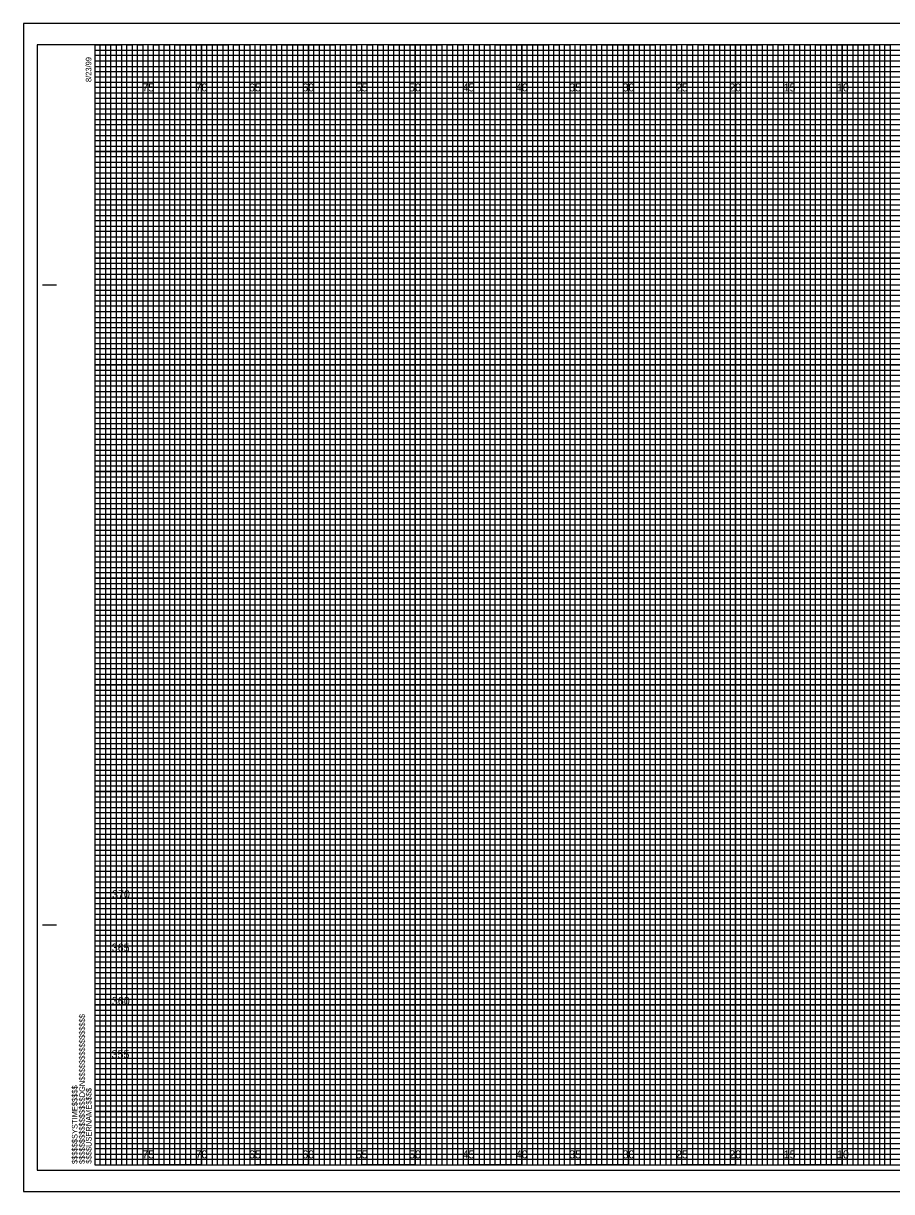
# Model space of a CAD drawing. Extents: x -7 to 266, y -5 to 437.
# Drawn here: x -6.7 to 74.6, y 327.5 to 437 of the extents above; entities that cross this region are included whole.
import ezdxf

# ---------------------------------------------------------------- set-up
doc = ezdxf.new("R2010")
doc.units = 0
for name, color, linetype in [('Exist XS Center Line Elevation Label', 7, 'Continuous'), ('Exist XS Ground Line', 7, 'Continuous'), ('Prop XS Finish Grade', 7, 'Continuous'), ('Prop XS Finish Grade Concrete', 7, 'Continuous'), ('Prop XS Finish Grade Earthwork', 7, 'Continuous'), ('Prop XS Hydro Elevations', 7, 'Continuous'), ('Prop XS Pvmt Edge Slope', 7, 'Continuous'), ('Prop XS SE Text', 7, 'Continuous'), ('Prop XS SS Elevation Text', 7, 'Continuous'), ('Prop XS Subgrade Earthwork', 7, 'Continuous'), ('Typical Guardrail CELL', 7, 'Continuous')]:
    doc.layers.add(name, color=color, linetype=linetype)

msp = doc.modelspace()

# ---------------------------------------------------------------- linework, layer by layer
at = {"layer": 'Exist XS Center Line Elevation Label'}
for points in [[(0, 435), (2.5, 435), (2.5, 330), (7.5, 330), (7.5, 435), (12.5, 435), (12.5, 330), (17.5, 330), (17.5, 435), (22.5, 435), (22.5, 330), (27.5, 330), (27.5, 435), (32.5, 435), (32.5, 330), (37.5, 330), (37.5, 435), (42.5, 435), (42.5, 330), (47.5, 330), (47.5, 435), (52.5, 435), (52.5, 330), (57.5, 330), (57.5, 435), (62.5, 435), (62.5, 330), (67.5, 330), (67.5, 435), (72.5, 435), (72.5, 330), (77.5, 330)], [(0, 432.5), (137.5, 432.5)], [(0, 422.5), (160, 422.5), (160, 427.5), (0, 427.5)], [(0, 412.5), (160, 412.5), (160, 417.5), (0, 417.5)], [(0, 402.5), (160, 402.5), (160, 407.5), (0, 407.5)], [(0, 392.5), (160, 392.5), (160, 397.5), (0, 397.5)], [(0, 382.5), (160, 382.5), (160, 387.5), (0, 387.5)], [(0, 372.5), (160, 372.5), (160, 377.5), (0, 377.5)], [(0, 362.5), (160, 362.5), (160, 367.5), (0, 367.5)], [(0, 352.5), (160, 352.5), (160, 357.5), (0, 357.5)], [(0, 342.5), (160, 342.5), (160, 347.5), (0, 347.5)], [(0, 332.5), (160, 332.5), (160, 337.5), (0, 337.5)]]:
    msp.add_lwpolyline(points, dxfattribs=at)
at = {"layer": 'Exist XS Ground Line'}
for p, q in [((5, 435), (0, 435)), ((5, 330), (5, 435)), ((15, 435), (10, 435)), ((10, 435), (10, 330)), ((15, 330), (15, 435)), ((25, 435), (20, 435)), ((20, 435), (20, 330)), ((25, 330), (25, 435)), ((35, 435), (30, 435)), ((30, 435), (30, 330)), ((35, 330), (35, 435)), ((45, 435), (40, 435)), ((40, 435), (40, 330)), ((45, 330), (45, 435)), ((55, 435), (50, 435)), ((50, 435), (50, 330)), ((55, 330), (55, 435)), ((65, 435), (60, 435)), ((60, 435), (60, 330)), ((65, 330), (65, 435)), ((75, 435), (70, 435)), ((70, 435), (70, 330)), ((10, 330), (5, 330)), ((20, 330), (15, 330)), ((30, 330), (25, 330)), ((40, 330), (35, 330)), ((50, 330), (45, 330)), ((60, 330), (55, 330)), ((70, 330), (65, 330))]:
    msp.add_line(p, q, dxfattribs=at)
for points in [[(0, 430), (160, 430), (160, 425), (0, 425)], [(0, 420), (160, 420), (160, 415), (0, 415)], [(0, 410), (160, 410), (160, 405), (0, 405)], [(0, 400), (160, 400), (160, 395), (0, 395)], [(0, 390), (160, 390), (160, 385), (0, 385)], [(0, 380), (160, 380), (160, 375), (0, 375)], [(0, 370), (160, 370), (160, 365), (0, 365)], [(0, 360), (160, 360), (160, 355), (0, 355)], [(0, 350), (160, 350), (160, 345), (0, 345)], [(0, 340), (160, 340), (160, 335), (0, 335)]]:
    msp.add_lwpolyline(points, dxfattribs=at)
at = {"layer": 'Prop XS Finish Grade'}
for p, q in [((5, 330), (5, 435)), ((10, 330), (10, 435)), ((15, 330), (15, 435)), ((20, 330), (20, 435)), ((25, 330), (25, 435)), ((30, 330), (30, 435)), ((35, 330), (35, 435)), ((40, 330), (40, 435)), ((45, 330), (45, 435)), ((50, 330), (50, 435)), ((55, 330), (55, 435)), ((60, 330), (60, 435)), ((65, 330), (65, 435)), ((70, 330), (70, 435)), ((0, 430), (160, 430)), ((0, 425), (160, 425)), ((0, 420), (160, 420)), ((0, 415), (160, 415)), ((0, 410), (160, 410)), ((0, 405), (160, 405)), ((0, 400), (160, 400)), ((0, 395), (160, 395)), ((0, 390), (160, 390)), ((0, 385), (160, 385)), ((0, 380), (160, 380)), ((0, 375), (160, 375)), ((0, 370), (160, 370)), ((0, 365), (160, 365)), ((0, 360), (160, 360)), ((0, 355), (160, 355)), ((0, 350), (160, 350)), ((0, 345), (160, 345)), ((0, 340), (160, 340)), ((0, 335), (160, 335))]:
    msp.add_line(p, q, dxfattribs=at)
at = {"layer": 'Prop XS Finish Grade Earthwork'}
msp.add_lwpolyline([(-6.7, 327.5), (161.65, 327.5), (161.65, 437), (-6.7, 437)], close=True, dxfattribs=at)
at = {"layer": 'Prop XS Hydro Elevations'}
for p, q in [((-4.9, 412.5), (-3.65, 412.5)), ((-4.85, 412.5), (-3.6, 412.5)), ((-4.9, 352.5), (-3.65, 352.5)), ((-4.85, 352.5), (-3.6, 352.5)), ((0, 330), (0, 330)), ((0, 330), (0, 330)), ((0, 330), (0, 330)), ((0, 330), (0, 330)), ((0, 330), (0, 330)), ((0, 330), (0, 330)), ((0, 330), (0, 330))]:
    msp.add_line(p, q, dxfattribs=at)
msp.add_lwpolyline([(160, 435), (0, 435), (0, 330), (160, 330)], close=True, dxfattribs=at)
at = {"layer": 'Prop XS Pvmt Edge Slope'}
msp.add_lwpolyline([(-5.4, 329.5), (161.2, 329.5), (161.2, 435), (-5.4, 435)], close=True, dxfattribs=at)
at = {"layer": 'Prop XS SE Text'}
for p, q in [((0, 434.5), (130, 434.5)), ((130, 433.99), (0, 433.99)), ((0, 433.99), (0, 433.5)), ((0, 433.5), (130, 433.5)), ((130, 432.94), (0, 432.94)), ((0, 432.94), (0, 432)), ((0, 432), (160, 432))]:
    msp.add_line(p, q, dxfattribs=at)
for points in [[(0, 431.5), (135, 431.5), (160, 431.5), (160, 431), (0, 431)], [(0, 430.5), (160, 430.5), (160, 429.5), (0, 429.5)], [(0, 429), (160, 429), (160, 428.5), (0, 428.49)], [(0, 428), (160, 428), (160, 427), (0, 427)], [(0, 426.5), (160, 426.5), (160, 426), (0, 426)], [(0, 425.5), (160, 425.5), (160, 424.5), (0, 424.5)], [(0, 424), (160, 424), (160, 423.5), (0, 423.5)], [(0, 423), (160, 423), (160, 422), (0, 422)], [(0, 421.5), (160, 421.5), (160, 421), (0, 421)], [(0, 420.5), (160, 420.5), (160, 419.5), (0, 419.5)], [(0, 419), (160, 419), (160, 418.5), (0, 418.5)], [(0, 418), (160, 418), (160, 416.98), (160, 416.5), (160, 416), (0, 416)], [(0, 417), (160, 417), (160, 416.5), (0, 416.5)], [(0, 415.5), (160, 415.5), (160, 414.5), (0, 414.51)], [(0, 414.51), (160, 414.5), (160, 414), (0, 414)], [(0, 413.5), (160, 413.5), (160, 413), (0, 413)], [(0, 412), (160, 412), (160, 411.5), (0, 411.5)], [(0, 411), (160, 411), (160, 410.5), (0, 410.5)], [(-0.04, 409.44), (160, 409.44), (160, 408.94), (-0.04, 408.94)], [(0, 408.5), (160, 408.5), (160, 408), (0, 408)], [(0, 407), (160, 407), (160, 406.5), (0, 406.5)], [(0, 406), (160, 406), (160, 405.5), (0, 405.5)], [(0, 404.5), (160, 404.5), (160, 404), (0, 404)], [(0, 403.5), (160, 403.5), (160, 403), (0, 403)], [(0, 402), (160, 402), (160, 401.5), (0, 401.5)], [(0, 401), (160, 401), (160, 400.5), (0, 400.5)], [(0, 399.5), (160, 399.5), (160, 398.99), (0, 399)], [(0, 398.5), (160, 398.5), (160, 398), (0, 398)], [(0, 397), (160, 397), (160, 396.5), (0, 396.5)], [(0, 396), (160, 396), (160, 395.5), (0, 395.5)], [(0, 394.5), (160, 394.5), (160, 394), (0, 394)], [(0, 393.5), (160, 393.5), (160, 393), (0, 393)], [(0, 392), (160, 392), (160, 391.5), (0, 391.5)], [(0, 391), (160, 391), (160, 390.5), (0, 390.5)], [(0, 389.5), (160, 389.5), (160, 389), (0, 389)], [(0, 388.5), (160.03, 388.45), (160, 388), (0, 388)], [(0, 387), (160, 387), (160, 386.5), (0, 386.5)], [(0, 386), (160, 386), (160, 385.5), (0, 385.5)], [(0, 384.5), (160, 384.5), (160, 384), (0, 384)], [(0, 383.5), (160, 383.5), (160, 383), (0, 383)], [(0, 382), (160, 382), (160, 381.5), (0, 381.5)], [(0, 381), (160, 381), (160, 380.5), (0, 380.5)], [(0, 379.5), (160, 379.5), (160, 379), (0, 379)], [(0, 378.5), (160, 378.5), (160, 378), (0, 378)], [(0, 377), (160, 377), (160, 376.5), (0, 376.5)], [(0, 376), (160, 376), (160, 375.5), (0, 375.5)], [(0, 374.5), (160, 374.5), (160, 374), (0, 374)], [(0, 373.5), (160, 373.5), (160, 373), (0, 373)], [(0, 372), (160, 372), (160, 371.5), (0, 371.5)], [(0, 371), (160, 371), (160, 370.5), (0, 370.5)], [(0, 369.5), (160, 369.5), (160, 368.99), (0, 369)], [(0, 368.5), (160, 368.5), (160, 368), (0, 368)], [(0, 367), (160, 367), (160, 366.5), (0, 366.5)], [(0, 366), (160, 366), (160, 365.5), (0, 365.5)], [(0, 364.5), (160, 364.5), (160, 364), (0, 364)], [(0, 363.5), (160, 363.5), (160, 363), (0, 363)], [(0, 362), (160, 362), (160, 361.5), (0, 361.5)], [(0, 361), (160, 361), (160, 360.5), (0, 360.5)], [(0, 359.5), (160, 359.5), (160, 359), (0, 359)], [(0, 358.5), (160.03, 358.45), (160, 358), (0, 358)], [(0, 357), (160, 357), (160, 356.5), (0, 356.5)], [(0, 356), (160, 356), (160, 355.5), (0, 355.5)], [(0, 354.5), (160, 354.5), (160, 354), (0, 354)], [(0, 353.5), (160, 353.5), (160, 353), (0, 353)], [(0, 352), (160, 352), (160, 351.5), (0, 351.5)], [(0, 351), (160, 351), (160, 350.5), (0, 350.5)], [(0, 349.5), (160, 349.5), (160, 349), (0, 349)], [(0, 348.5), (160, 348.5), (160, 348), (0, 348)], [(0, 347), (160, 347), (160, 346.5), (0, 346.5)], [(0, 346), (160, 346), (160, 345.5), (0, 345.5)], [(0, 344.5), (160, 344.5), (160, 344), (0, 344)], [(0, 343.5), (160, 343.5), (160, 343), (0, 343)], [(0, 342), (160, 342), (160, 341.5), (0, 341.5)], [(0, 341), (160, 341), (160, 340.5), (0, 340.5)], [(0, 339.5), (160, 339.5), (160, 339), (0, 339)], [(0, 338.5), (160, 338.5), (160, 338), (0, 338)], [(0, 337), (160, 337), (160, 336.5), (0, 336.5)], [(0, 336), (160, 336), (160, 335.5), (0, 335.5)], [(0, 334.5), (160, 334.5), (160, 334), (0, 334)], [(0, 333.5), (160, 333.5), (160, 333), (0, 333)], [(0, 332), (160, 332), (160, 331.5), (0, 331.5)], [(0, 331), (160, 331), (160, 330.5), (0, 330.5)]]:
    msp.add_lwpolyline(points, dxfattribs=at)
at = {"layer": 'Prop XS SS Elevation Text'}
for points in [[(0, 330), (0.5, 330), (0.5, 435), (1, 435), (1, 330)], [(1, 330), (1.5, 330), (1.5, 435), (2, 435), (2, 330)], [(2.5, 330), (3, 330), (3, 435), (3.5, 435), (3.5, 330)], [(3.5, 330), (4, 330), (4, 435), (4.5, 435), (4.5, 330)], [(5, 330), (5.5, 330), (5.5, 435), (6, 435), (6, 330)], [(6, 330), (6.5, 330), (6.5, 435), (7, 435), (7, 330)], [(7.5, 330), (8, 330), (8, 435), (8.5, 435), (8.5, 330)], [(8.5, 330), (9, 330), (9, 435), (9.5, 435), (9.5, 330)], [(10, 330), (10.5, 330), (10.5, 435), (11, 435), (11, 330)], [(11, 330), (11.5, 330), (11.5, 435), (12, 435), (12, 330)], [(12.5, 330), (13, 330), (13, 435), (13.5, 435), (13.5, 330)], [(13.5, 330), (14, 330), (14, 435), (14.5, 435), (14.5, 330)], [(15, 330), (15.5, 330), (15.5, 435), (16, 435), (16, 330)], [(16, 330), (16.5, 330), (16.5, 435), (17, 435), (17, 330)], [(17.5, 330), (18, 330), (18, 435), (18.5, 435), (18.5, 330)], [(18.5, 330), (19, 330), (19, 435), (19.5, 435), (19.5, 330)], [(20, 330), (20.5, 330), (20.5, 435), (21, 435), (21, 330)], [(21, 330), (21.5, 330), (21.5, 435), (22, 435), (22, 330)], [(22.5, 330), (23, 330), (23, 435), (23.5, 435), (23.5, 330)], [(23.5, 330), (24, 330), (24, 435), (24.5, 435), (24.5, 330)], [(25, 330), (25.5, 330), (25.5, 435), (26, 435), (26, 330)], [(26, 330), (26.5, 330), (26.5, 435), (27, 435), (27, 330)], [(27.5, 330), (28, 330), (28, 435), (28.5, 435), (28.5, 330)], [(28.5, 330), (29, 330), (29, 435), (29.5, 435), (29.5, 330)], [(30, 330), (30.5, 330), (30.5, 435), (31, 435), (31, 330)], [(31, 330), (31.5, 330), (31.5, 435), (32, 435), (32, 330)], [(32.5, 330), (33, 330), (33, 435), (33.5, 435), (33.5, 330)], [(33.5, 330), (34, 330), (34, 435), (34.5, 435), (34.5, 330)], [(35, 330), (35.5, 330), (35.5, 435), (36, 435), (36, 330)], [(36, 330), (36.5, 330), (36.5, 435), (37, 435), (37, 330)], [(37.5, 330), (38, 330), (38, 435), (38.5, 435), (38.5, 330)], [(38.5, 330), (39, 330), (39, 435), (39.5, 435), (39.5, 330)], [(40, 330), (40.5, 330), (40.5, 435), (41, 435), (41, 330)], [(41, 330), (41.5, 330), (41.5, 435), (42, 435), (42, 330)], [(42.5, 330), (43, 330), (43, 435), (43.5, 435), (43.5, 330)], [(43.5, 330), (44, 330), (44, 435), (44.5, 435), (44.5, 330)], [(45, 330), (45.5, 330), (45.5, 435), (46, 435), (46, 330)], [(46, 330), (46.5, 330), (46.5, 435), (47, 435), (47, 330)], [(47.5, 330), (48, 330), (48, 435), (48.5, 435), (48.5, 330)], [(48.5, 330), (49, 330), (49, 435), (49.5, 435), (49.5, 330)], [(50, 330), (50.5, 330), (50.5, 435), (51, 435), (51, 330)], [(51, 330), (51.5, 330), (51.5, 435), (52, 435), (52, 330)], [(52.5, 330), (53, 330), (53, 435), (53.5, 435), (53.5, 330)], [(53.5, 330), (54, 330), (54, 435), (54.5, 435), (54.5, 330)], [(55, 330), (55.5, 330), (55.5, 435), (56, 435), (56, 330)], [(56, 330), (56.5, 330), (56.5, 435), (57, 435), (57, 330)], [(57.5, 330), (58, 330), (58, 435), (58.5, 435), (58.5, 330)], [(58.5, 330), (59, 330), (59, 435), (59.5, 435), (59.5, 330)], [(60, 330), (60.5, 330), (60.5, 435), (61, 435), (61, 330)], [(61, 330), (61.5, 330), (61.5, 435), (62, 435), (62, 330)], [(62.5, 330), (63, 330), (63, 435), (63.5, 435), (63.5, 330)], [(63.5, 330), (64, 330), (64, 435), (64.5, 435), (64.5, 330)], [(65, 330), (65.5, 330), (65.5, 435), (66, 435), (66, 330)], [(66, 330), (66.5, 330), (66.5, 435), (67, 435), (67, 330)], [(67.5, 330), (68, 330), (68, 435), (68.5, 435), (68.5, 330)], [(68.5, 330), (69, 330), (69, 435), (69.5, 435), (69.5, 330)], [(70, 330), (70.5, 330), (70.5, 435), (71, 435), (71, 330)], [(71, 330), (71.5, 330), (71.5, 435), (72, 435), (72, 330)], [(72.5, 330), (73, 330), (73, 435), (73.5, 435), (73.5, 330)], [(73.5, 330), (74, 330), (74, 435), (74.5, 435), (74.5, 330)]]:
    msp.add_lwpolyline(points, dxfattribs=at)
at = {"layer": 'Prop XS Subgrade Earthwork'}
for p, q in [((161.65, 437), (-6.7, 437)), ((-6.7, 437), (-6.7, 327.5)), ((-6.7, 327.5), (161.65, 327.5))]:
    msp.add_line(p, q, dxfattribs=at)

# ---------------------------------------------------------------- texts
at = {"layer": 'Prop XS Finish Grade Concrete'}
for s, p in [('370', (1.61, 355)), ('365', (1.58, 350)), ('360', (1.59, 345)), ('355', (1.56, 340))]:
    msp.add_text(s, height=0.75, dxfattribs=at).set_placement(p)
at = {"layer": 'Prop XS Hydro Elevations'}
for s, p in [('8/23/99', (-0.33, 431.5)), ('$$$$$$$$$$$$$$$$DGN$$$$$$$$$$$$$$$$', (-0.94, 330.09)), ('$$$$$$SYSTIME$$$$$', (-1.63, 330.09)), ('$$$$USERNAME$$$$', (-0.31, 330.12))]:
    msp.add_text(s, height=0.525, rotation=90, dxfattribs=at).set_placement(p)
at = {"layer": 'Typical Guardrail CELL'}
for s, p in [('75', (4.44, 430.62)), ('70', (9.43, 430.62)), ('65', (14.44, 430.62)), ('60', (19.43, 430.62)), ('55', (24.44, 430.62)), ('50', (29.43, 430.62)), ('45', (34.44, 430.62)), ('40', (39.43, 430.62)), ('35', (44.44, 430.62)), ('30', (49.43, 430.62)), ('25', (54.44, 430.62)), ('20', (59.43, 430.62)), ('15', (64.53, 430.62)), ('10', (69.52, 430.62)), ('75', (4.44, 330.62)), ('70', (9.43, 330.62)), ('65', (14.44, 330.62)), ('60', (19.43, 330.62)), ('55', (24.44, 330.62)), ('50', (29.43, 330.62)), ('45', (34.44, 330.62)), ('40', (39.43, 330.62)), ('35', (44.44, 330.62)), ('30', (49.43, 330.62)), ('25', (54.44, 330.62)), ('20', (59.43, 330.62)), ('15', (64.53, 330.62)), ('10', (69.52, 330.62))]:
    msp.add_text(s, height=0.75, dxfattribs=at).set_placement(p)

doc.saveas('drawing.dxf')
